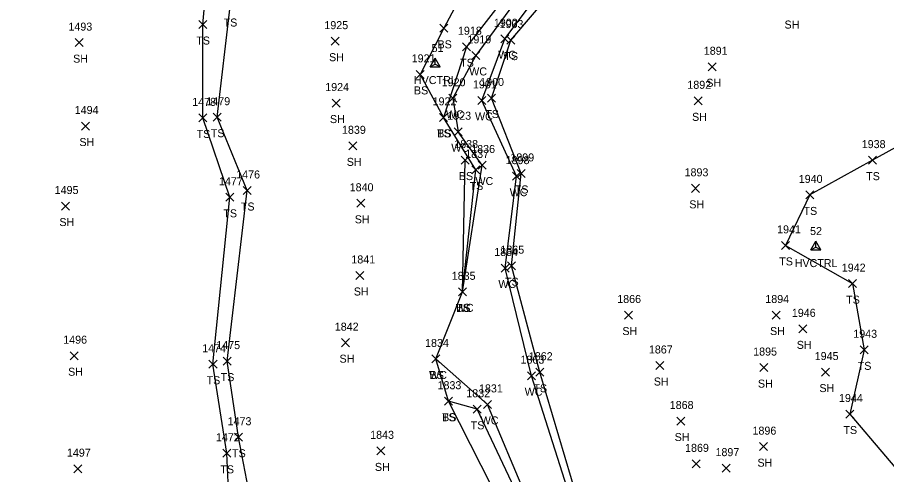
# Model space of a CAD drawing. Extents: x 1754529 to 1755810, y 621660 to 624656.
# Drawn here: x 1755027.6 to 1755244.8, y 624220.4 to 624334.6 of the extents above; entities that cross this region are included whole.
import ezdxf

# ---------------------------------------------------------------- set-up
doc = ezdxf.new("R2010")
doc.units = 0
for name, color, linetype in [('C_A', 7, 'Continuous'), ('C_I', 7, 'Continuous'), ('CPSM', 7, 'Continuous'), ('L_A', 7, 'Continuous'), ('L_I', 7, 'Continuous'), ('L_TIC', 7, 'Continuous'), ('LAWE', 7, 'Continuous'), ('LELB', 7, 'Continuous')]:
    doc.layers.add(name, color=color, linetype=linetype)

msp = doc.modelspace()

# ---------------------------------------------------------------- linework, layer by layer
at = {"layer": 'CPSM'}
for p, q in [((1755130.77, 624322.19), (1755132.02, 624324.36)), ((1755133.27, 624322.19), (1755132.02, 624324.36)), ((1755132.02, 624322.91), (1755132.02, 624324.36)), ((1755130.77, 624322.19), (1755132.02, 624322.91)), ((1755130.77, 624322.19), (1755133.27, 624322.19)), ((1755132.02, 624322.91), (1755132.02, 624322.91)), ((1755132.02, 624322.91), (1755133.27, 624322.19)), ((1755225.89, 624276.5), (1755227.14, 624278.66)), ((1755228.39, 624276.5), (1755227.14, 624278.66)), ((1755227.15, 624277.22), (1755227.14, 624278.66)), ((1755225.89, 624276.5), (1755227.15, 624277.22)), ((1755225.89, 624276.5), (1755228.39, 624276.5)), ((1755227.15, 624277.22), (1755227.15, 624277.22)), ((1755227.15, 624277.22), (1755228.39, 624276.5))]:
    msp.add_line(p, q, dxfattribs=at)
at = {"layer": 'L_TIC'}
for points in [[(1755072.93, 624331.78), (1755074.93, 624333.78)], [(1755074.93, 624331.78), (1755072.93, 624333.78)], [(1755133.16, 624330.83), (1755135.16, 624332.83)], [(1755135.16, 624330.83), (1755133.16, 624332.83)], [(1755106.02, 624327.62), (1755108.02, 624329.62)], [(1755108.02, 624327.62), (1755106.02, 624329.62)], [(1755148.45, 624328.22), (1755150.45, 624330.22)], [(1755150.45, 624328.22), (1755148.45, 624330.22)], [(1755149.89, 624327.89), (1755151.89, 624329.89)], [(1755151.89, 624327.89), (1755149.89, 624329.89)], [(1755042.09, 624327.26), (1755044.09, 624329.26)], [(1755044.09, 624327.26), (1755042.09, 624329.26)], [(1755138.84, 624326.23), (1755140.84, 624328.23)], [(1755140.84, 624326.23), (1755138.84, 624328.23)], [(1755141.21, 624324.07), (1755143.21, 624326.07)], [(1755143.21, 624324.07), (1755141.21, 624326.07)], [(1755200.26, 624321.23), (1755202.26, 624323.23)], [(1755202.26, 624321.23), (1755200.26, 624323.23)], [(1755127.27, 624319.33), (1755129.27, 624321.33)], [(1755129.27, 624319.33), (1755127.27, 624321.33)], [(1755135.43, 624313.36), (1755137.43, 624315.36)], [(1755137.43, 624313.36), (1755135.43, 624315.36)], [(1755142.66, 624312.83), (1755144.66, 624314.83)], [(1755144.66, 624312.83), (1755142.66, 624314.83)], [(1755145.12, 624313.43), (1755147.12, 624315.43)], [(1755147.12, 624313.43), (1755145.12, 624315.43)], [(1755196.72, 624312.73), (1755198.72, 624314.73)], [(1755198.72, 624312.73), (1755196.72, 624314.73)], [(1755106.25, 624312.17), (1755108.25, 624314.17)], [(1755108.25, 624312.17), (1755106.25, 624314.17)], [(1755073.01, 624308.47), (1755075.01, 624310.47)], [(1755075.01, 624308.47), (1755073.01, 624310.47)], [(1755076.56, 624308.64), (1755078.56, 624310.64)], [(1755078.56, 624308.64), (1755076.56, 624310.64)], [(1755133.08, 624308.6), (1755135.08, 624310.6)], [(1755135.08, 624308.6), (1755133.08, 624310.6)], [(1755133.08, 624308.6), (1755135.08, 624310.6)], [(1755135.08, 624308.6), (1755133.08, 624310.6)], [(1755133.08, 624308.6), (1755135.08, 624310.6)], [(1755135.08, 624308.6), (1755133.08, 624310.6)], [(1755043.65, 624306.44), (1755045.65, 624308.44)], [(1755045.65, 624306.44), (1755043.65, 624308.44)], [(1755136.75, 624305.01), (1755138.75, 624307.01)], [(1755138.75, 624305.01), (1755136.75, 624307.01)], [(1755136.75, 624305.01), (1755138.75, 624307.01)], [(1755138.75, 624305.01), (1755136.75, 624307.01)], [(1755110.44, 624301.49), (1755112.44, 624303.49)], [(1755112.44, 624301.49), (1755110.44, 624303.49)], [(1755138.48, 624297.94), (1755140.48, 624299.94)], [(1755140.48, 624297.94), (1755138.48, 624299.94)], [(1755240.28, 624297.92), (1755242.28, 624299.92)], [(1755242.28, 624297.92), (1755240.28, 624299.92)], [(1755141.21, 624295.47), (1755143.21, 624297.47)], [(1755143.21, 624295.47), (1755141.21, 624297.47)], [(1755142.77, 624296.7), (1755144.77, 624298.7)], [(1755144.77, 624296.7), (1755142.77, 624298.7)], [(1755151.32, 624293.92), (1755153.32, 624295.92)], [(1755153.32, 624293.92), (1755151.32, 624295.92)], [(1755152.5, 624294.6), (1755154.5, 624296.6)], [(1755154.5, 624294.6), (1755152.5, 624296.6)], [(1755196.02, 624290.88), (1755198.02, 624292.88)], [(1755198.02, 624290.88), (1755196.02, 624292.88)], [(1755079.69, 624288.64), (1755081.69, 624290.64)], [(1755081.69, 624288.64), (1755079.69, 624290.64)], [(1755084.06, 624290.34), (1755086.06, 624292.34)], [(1755086.06, 624290.34), (1755084.06, 624292.34)], [(1755224.63, 624289.24), (1755226.63, 624291.24)], [(1755226.63, 624289.24), (1755224.63, 624291.24)], [(1755038.64, 624286.46), (1755040.64, 624288.46)], [(1755040.64, 624286.46), (1755038.64, 624288.46)], [(1755112.44, 624287.15), (1755114.44, 624289.15)], [(1755114.44, 624287.15), (1755112.44, 624289.15)], [(1755218.57, 624276.64), (1755220.57, 624278.64)], [(1755220.57, 624276.64), (1755218.57, 624278.64)], [(1755150.05, 624271.57), (1755152.05, 624273.57)], [(1755152.05, 624271.57), (1755150.05, 624273.57)], [(1755112.2, 624269.13), (1755114.2, 624271.13)], [(1755114.2, 624269.13), (1755112.2, 624271.13)], [(1755148.51, 624270.99), (1755150.51, 624272.99)], [(1755150.51, 624270.99), (1755148.51, 624272.99)], [(1755235.29, 624267.09), (1755237.29, 624269.09)], [(1755237.29, 624267.09), (1755235.29, 624269.09)], [(1755137.85, 624265.04), (1755139.85, 624267.04)], [(1755139.85, 624265.04), (1755137.85, 624267.04)], [(1755137.85, 624265.04), (1755139.85, 624267.04)], [(1755139.85, 624265.04), (1755137.85, 624267.04)], [(1755137.85, 624265.04), (1755139.85, 624267.04)], [(1755139.85, 624265.04), (1755137.85, 624267.04)], [(1755179.3, 624259.25), (1755181.3, 624261.25)], [(1755181.3, 624259.25), (1755179.3, 624261.25)], [(1755216.19, 624259.25), (1755218.19, 624261.25)], [(1755218.19, 624259.25), (1755216.19, 624261.25)], [(1755222.87, 624255.8), (1755224.87, 624257.8)], [(1755224.87, 624255.8), (1755222.87, 624257.8)], [(1755108.63, 624252.35), (1755110.63, 624254.35)], [(1755110.63, 624252.35), (1755108.63, 624254.35)], [(1755238.17, 624250.56), (1755240.17, 624252.56)], [(1755240.17, 624250.56), (1755238.17, 624252.56)], [(1755040.83, 624249.09), (1755042.83, 624251.09)], [(1755042.83, 624249.09), (1755040.83, 624251.09)], [(1755079.02, 624247.74), (1755081.02, 624249.74)], [(1755081.02, 624247.74), (1755079.02, 624249.74)], [(1755131.18, 624248.28), (1755133.18, 624250.28)], [(1755133.18, 624248.28), (1755131.18, 624250.28)], [(1755131.18, 624248.28), (1755133.18, 624250.28)], [(1755133.18, 624248.28), (1755131.18, 624250.28)], [(1755075.51, 624246.96), (1755077.51, 624248.96)], [(1755077.51, 624246.96), (1755075.51, 624248.96)], [(1755187.15, 624246.65), (1755189.15, 624248.65)], [(1755189.15, 624246.65), (1755187.15, 624248.65)], [(1755213.16, 624246.13), (1755215.16, 624248.13)], [(1755215.16, 624246.13), (1755213.16, 624248.13)], [(1755155.07, 624244.11), (1755157.07, 624246.11)], [(1755157.07, 624244.11), (1755155.07, 624246.11)], [(1755157.15, 624244.97), (1755159.15, 624246.97)], [(1755159.15, 624244.97), (1755157.15, 624246.97)], [(1755228.54, 624245.01), (1755230.54, 624247.01)], [(1755230.54, 624245.01), (1755228.54, 624247.01)], [(1755134.31, 624237.73), (1755136.31, 624239.73)], [(1755136.31, 624237.73), (1755134.31, 624239.73)], [(1755134.31, 624237.73), (1755136.31, 624239.73)], [(1755136.31, 624237.73), (1755134.31, 624239.73)], [(1755144.09, 624236.93), (1755146.09, 624238.93)], [(1755146.09, 624236.93), (1755144.09, 624238.93)], [(1755141.49, 624235.72), (1755143.49, 624237.72)], [(1755143.49, 624235.72), (1755141.49, 624237.72)], [(1755234.61, 624234.54), (1755236.61, 624236.54)], [(1755236.61, 624234.54), (1755234.61, 624236.54)], [(1755192.36, 624232.79), (1755194.36, 624234.79)], [(1755194.36, 624232.79), (1755192.36, 624234.79)], [(1755081.86, 624228.74), (1755083.86, 624230.74)], [(1755083.86, 624228.74), (1755081.86, 624230.74)], [(1755213.05, 624226.39), (1755215.05, 624228.39)], [(1755215.05, 624226.39), (1755213.05, 624228.39)], [(1755078.94, 624224.73), (1755080.94, 624226.73)], [(1755080.94, 624224.73), (1755078.94, 624226.73)], [(1755117.47, 624225.34), (1755119.47, 624227.34)], [(1755119.47, 624225.34), (1755117.47, 624227.34)], [(1755196.2, 624222.09), (1755198.2, 624224.09)], [(1755198.2, 624222.09), (1755196.2, 624224.09)], [(1755041.71, 624220.89), (1755043.71, 624222.89)], [(1755043.71, 624220.89), (1755041.71, 624222.89)], [(1755203.75, 624221.02), (1755205.75, 624223.02)], [(1755205.75, 624221.02), (1755203.75, 624223.02)]]:
    msp.add_lwpolyline(points, dxfattribs=at)
at = {"layer": 'LAWE'}
for points in [[(1755205.67, 624376.28), (1755175.49, 624362.73), (1755163.49, 624354.18), (1755142.21, 624325.07), (1755136.43, 624314.36), (1755137.75, 624306.01)], [(1755173.74, 623956.25), (1755179.49, 623981.26), (1755189.19, 624018.36), (1755179.71, 624027.81), (1755177.17, 624037.31), (1755183.05, 624071.07), (1755186.59, 624109.3), (1755195.76, 624123.49), (1755204.15, 624140.63), (1755199.7, 624157.52), (1755189.07, 624181.84), (1755178.94, 624196.44), (1755167.9, 624207.95), (1755156.07, 624245.11), (1755149.51, 624271.99), (1755152.32, 624294.92), (1755143.66, 624313.83), (1755149.45, 624329.22), (1755168.42, 624354.45), (1755209.86, 624368.35), (1755209.13, 624369.86)], [(1755172.44, 623956.64), (1755176.98, 623981.31), (1755183.44, 624014.66), (1755174.17, 624039.77), (1755180.5, 624069.56), (1755183.04, 624107.8), (1755193.55, 624125.22), (1755195.6, 624144.75), (1755194.59, 624151.24), (1755197.16, 624154.94), (1755178.66, 624184.32), (1755154.86, 624214.79), (1755145.09, 624237.93), (1755132.18, 624249.28), (1755138.85, 624266.04), (1755143.77, 624297.7), (1755137.75, 624306.01)]]:
    msp.add_lwpolyline(points, dxfattribs=at)
at = {"layer": 'LELB'}
for points in [[(1755139.04, 624115.61), (1755146.37, 624123.46), (1755138.82, 624137.58), (1755123.57, 624162.31), (1755113.43, 624179.53), (1755086.23, 624212.44), (1755082.86, 624229.74), (1755080.02, 624248.74), (1755085.06, 624291.34), (1755077.56, 624309.64), (1755080.76, 624337.28), (1755079.75, 624370.72), (1755071.03, 624399.94), (1755077.76, 624423.68)], [(1755139.04, 624115.61), (1755135.04, 624134.99), (1755120.88, 624159.14), (1755108.49, 624174.55), (1755081.03, 624201.93), (1755079.94, 624225.73), (1755076.51, 624247.96), (1755080.69, 624289.64), (1755074.01, 624309.47), (1755073.93, 624332.78), (1755077.13, 624367.68), (1755065.05, 624394.38), (1755036.59, 624410.3), (1755018.14, 624419.38)], [(1755204.81, 624379.16), (1755173.81, 624368.42), (1755162.16, 624355.98), (1755139.84, 624327.23), (1755134.08, 624309.6)], [(1755162.16, 624355.98), (1755147.37, 624356.62), (1755134.16, 624331.83), (1755128.27, 624320.33), (1755134.08, 624309.6)], [(1755179.93, 623958.52), (1755184.68, 623980.7), (1755191.18, 624019.58), (1755181.19, 624028.74), (1755178.62, 624037.28), (1755185, 624070.71), (1755187.96, 624108.96), (1755197.92, 624122.33), (1755209.55, 624141.51), (1755204.36, 624157.97), (1755190.25, 624182.31), (1755180.73, 624197.48), (1755169.22, 624208.69), (1755158.15, 624245.97), (1755151.05, 624272.57), (1755153.5, 624295.6), (1755146.12, 624314.43), (1755150.89, 624328.89), (1755170.15, 624351.46)], [(1755283.63, 624321.58), (1755261.89, 624310.21), (1755241.28, 624298.92), (1755225.63, 624290.24), (1755219.57, 624277.64), (1755236.29, 624268.09), (1755239.17, 624251.56), (1755235.61, 624235.54), (1755253.41, 624214.52), (1755275.93, 624188.95), (1755280.26, 624179.83), (1755294.83, 624178.69), (1755307.15, 624169.54), (1755309.03, 624155.09), (1755307.67, 624133.57), (1755296.24, 624106.15), (1755299.26, 624064.9), (1755318.78, 624037.89), (1755344, 624017.13), (1755370, 623994.13), (1755389.34, 623965.32), (1755402.54, 623944.92), (1755412.5, 623921.31), (1755426.67, 623899.96)], [(1755138.85, 624266.04), (1755142.21, 624296.47), (1755134.08, 624309.6)], [(1755138.85, 624266.04), (1755139.48, 624298.94)], [(1755188.6, 624143.32), (1755167.17, 624176.49), (1755149.02, 624211.86), (1755135.31, 624238.73), (1755132.18, 624249.28)], [(1755170.6, 623960.85), (1755174.73, 623982.17), (1755180.73, 624013.57), (1755171.3, 624040.04), (1755179.35, 624069.6), (1755180.41, 624106.3), (1755192.02, 624127.09), (1755193.84, 624144.56), (1755192.95, 624151.67), (1755195.38, 624154.8), (1755176.76, 624182.9), (1755153.26, 624214.03), (1755142.49, 624236.72), (1755135.31, 624238.73)]]:
    msp.add_lwpolyline(points, dxfattribs=at)

# ---------------------------------------------------------------- texts
at = {"layer": 'C_A'}
for p in [(1755126.71, 624317.91), (1755221.84, 624272.22)]:
    msp.add_text('HVCTRL', height=2, dxfattribs=at).set_placement(p)
at = {"layer": 'C_I'}
for s, p in [('51', (1755131.12, 624325.91)), ('52', (1755225.68, 624280.22))]:
    msp.add_text(s, height=2, dxfattribs=at).set_placement(p)
at = {"layer": 'L_A'}
for s, p in [('TS', (1755079.17, 624332.28)), ('SH', (1755219.3, 624331.77)), ('TS', (1755072.34, 624327.78)), ('BS', (1755132.6, 624326.83)), ('SH', (1755041.57, 624323.26)), ('SH', (1755105.51, 624323.62)), ('WC', (1755147.76, 624324.22)), ('TS', (1755149.3, 624323.89)), ('TS', (1755138.25, 624322.23)), ('WC', (1755140.52, 624320.07)), ('SH', (1755199.75, 624317.23)), ('BS', (1755126.71, 624315.33)), ('SH', (1755105.73, 624308.17)), ('WC', (1755134.74, 624309.36)), ('WC', (1755141.97, 624308.83)), ('TS', (1755144.53, 624309.43)), ('SH', (1755196.2, 624308.73)), ('TS', (1755072.42, 624304.47)), ('TS', (1755075.96, 624304.64)), ('TS', (1755132.48, 624304.6)), ('TS', (1755132.48, 624304.6)), ('BS', (1755132.52, 624304.6)), ('SH', (1755043.14, 624302.44)), ('WC', (1755136.05, 624301.01)), ('WC', (1755136.05, 624301.01)), ('SH', (1755109.93, 624297.49)), ('BS', (1755137.92, 624293.94)), ('TS', (1755239.69, 624293.92)), ('TS', (1755140.62, 624291.47)), ('WC', (1755142.08, 624292.7)), ('WC', (1755150.63, 624289.92)), ('TS', (1755151.91, 624290.6)), ('TS', (1755083.47, 624286.34)), ('SH', (1755195.51, 624286.88)), ('TS', (1755079.1, 624284.64)), ('TS', (1755224.04, 624285.24)), ('SH', (1755038.13, 624282.46)), ('SH', (1755111.93, 624283.15)), ('TS', (1755217.98, 624272.64)), ('WC', (1755147.81, 624266.99)), ('TS', (1755149.46, 624267.57)), ('SH', (1755111.69, 624265.13)), ('TS', (1755234.7, 624263.09)), ('WC', (1755137.16, 624261.04)), ('TS', (1755137.26, 624261.04)), ('BS', (1755137.29, 624261.04)), ('SH', (1755178.79, 624255.25)), ('SH', (1755215.68, 624255.25)), ('SH', (1755222.36, 624251.8)), ('SH', (1755108.12, 624248.35)), ('SH', (1755040.32, 624245.09)), ('TS', (1755237.58, 624246.56)), ('TS', (1755074.92, 624242.96)), ('TS', (1755078.43, 624243.74)), ('WC', (1755130.49, 624244.28)), ('BS', (1755130.62, 624244.28)), ('TS', (1755156.56, 624240.97)), ('SH', (1755186.64, 624242.65)), ('SH', (1755212.65, 624242.13)), ('SH', (1755228.02, 624241.01)), ('WC', (1755154.38, 624240.11)), ('TS', (1755133.72, 624233.73)), ('BS', (1755133.75, 624233.73)), ('WC', (1755143.39, 624232.93)), ('TS', (1755140.9, 624231.72)), ('TS', (1755234.01, 624230.54)), ('SH', (1755191.85, 624228.79)), ('TS', (1755081.27, 624224.74)), ('SH', (1755116.96, 624221.34)), ('SH', (1755212.54, 624222.39)), ('TS', (1755078.35, 624220.73))]:
    msp.add_text(s, height=2, dxfattribs=at).set_placement(p)
at = {"layer": 'L_I'}
for s, p in [('1902', (1755146.68, 624332.22)), ('1903', (1755148.11, 624331.89)), ('1493', (1755040.39, 624331.26)), ('1925', (1755104.33, 624331.62)), ('1918', (1755137.71, 624330.23)), ('1919', (1755140.08, 624328.07)), ('1921', (1755126.15, 624323.33)), ('1891', (1755199.13, 624325.23)), ('1920', (1755133.65, 624317.36)), ('1901', (1755141.45, 624316.83)), ('1900', (1755143.26, 624317.43)), ('1892', (1755195.02, 624316.73)), ('1924', (1755104.55, 624316.17)), ('1478', (1755071.32, 624312.47)), ('1479', (1755074.85, 624312.64)), ('1922', (1755131.38, 624312.6)), ('1922', (1755131.38, 624312.6)), ('1922', (1755131.38, 624312.6)), ('1494', (1755041.96, 624310.44)), ('1923', (1755135.05, 624309.01)), ('1923', (1755135.05, 624309.01)), ('1839', (1755108.74, 624305.49)), ('1838', (1755136.78, 624301.94)), ('1938', (1755238.59, 624301.92)), ('1837', (1755139.52, 624299.47)), ('1836', (1755141.03, 624300.7)), ('1898', (1755149.63, 624297.92)), ('1899', (1755150.8, 624298.6)), ('1476', (1755082.31, 624294.34)), ('1893', (1755194.33, 624294.88)), ('1940', (1755222.85, 624293.24)), ('1477', (1755078, 624292.64)), ('1840', (1755110.66, 624291.15)), ('1495', (1755036.95, 624290.46)), ('1941', (1755217.45, 624280.64)), ('1865', (1755148.31, 624275.57)), ('1864', (1755146.77, 624274.99)), ('1841', (1755111.07, 624273.13)), ('1942', (1755233.6, 624271.09)), ('1835', (1755136.16, 624269.04)), ('1835', (1755136.16, 624269.04)), ('1835', (1755136.16, 624269.04)), ('1866', (1755177.5, 624263.25)), ('1894', (1755214.5, 624263.25)), ('1946', (1755221.13, 624259.8)), ('1842', (1755106.94, 624256.35)), ('1943', (1755236.47, 624254.56)), ('1496', (1755039.09, 624253.09)), ('1475', (1755077.33, 624251.74)), ('1834', (1755129.49, 624252.28)), ('1834', (1755129.49, 624252.28)), ('1474', (1755073.82, 624250.96)), ('1867', (1755185.41, 624250.65)), ('1895', (1755211.47, 624250.13)), ('1863', (1755153.33, 624248.11)), ('1862', (1755155.41, 624248.97)), ('1945', (1755226.84, 624249.01)), ('1833', (1755132.61, 624241.73)), ('1833', (1755132.61, 624241.73)), ('1831', (1755142.96, 624240.93)), ('1832', (1755139.8, 624239.72)), ('1944', (1755232.91, 624238.54)), ('1868', (1755190.62, 624236.79)), ('1473', (1755080.16, 624232.74)), ('1896', (1755211.3, 624230.39)), ('1472', (1755077.25, 624228.73)), ('1843', (1755115.78, 624229.34)), ('1869', (1755194.45, 624226.09)), ('1497', (1755040.02, 624224.89)), ('1897', (1755202.05, 624225.02))]:
    msp.add_text(s, height=2, dxfattribs=at).set_placement(p)

doc.saveas('drawing.dxf')
